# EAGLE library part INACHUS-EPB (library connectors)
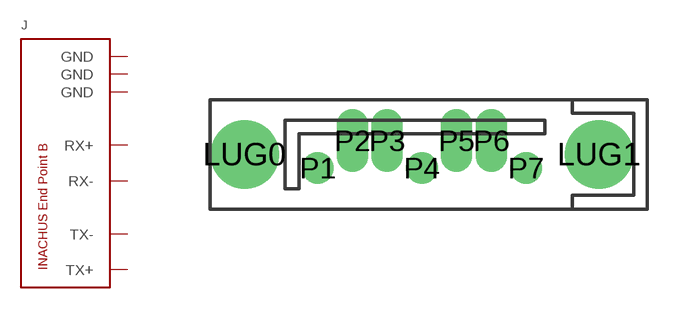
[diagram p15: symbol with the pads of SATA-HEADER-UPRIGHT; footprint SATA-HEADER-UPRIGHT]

Designator prefix J

## INACHUS-EPBUPRIGHT  [SATA-HEADER-UPRIGHT]
P1  GND  pwr
P2  TX+  out
P3  TX-  out
P4  GND  pwr
P5  RX-  in
P6  RX+  in
P7  GND  pwr

## Footprint SATA-HEADER-UPRIGHT (pad centres in mm)
drill 1.25 pad 2.5 round: LUG0 -6.48,0; LUG1 6.48,0
drill 0.65 pad 1.1 round: P1 -3.81,-0.5; P4 0,-0.5; P7 3.81,-0.5
drill 0.65 pad 1 long: P2 -2.54,0.5; P3 -1.27,0.5; P5 1.27,0.5; P6 2.54,0.5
